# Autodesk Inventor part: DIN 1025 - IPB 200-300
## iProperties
Created: 2007-02
Part Number: DIN 1025 - IPB 200-300
Material: Stahl, weich, unlegiert
Description: Warmgewalzte I-Träger IPB
Document SubType Name: Modeling
Standard: DIN 1025
Designer: thomas
Standards Organization: DIN
Language: de-DE
Size Designation: IPB 200-300
Categories: <MemberInstance><Categories><Category DisplayName="Profilstähle" InternalName="089c4875-fa83-4c05-b084-43b9cc11f5ed" Mnemonic="GRDR"><CategoryParameter DisplayN
Stock Number: IPB 200
Density: 7.86 g/cm^3
G_L: 300,000 mm
IsCustomPart: 1
Author: thomas
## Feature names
1. Extrusion1
